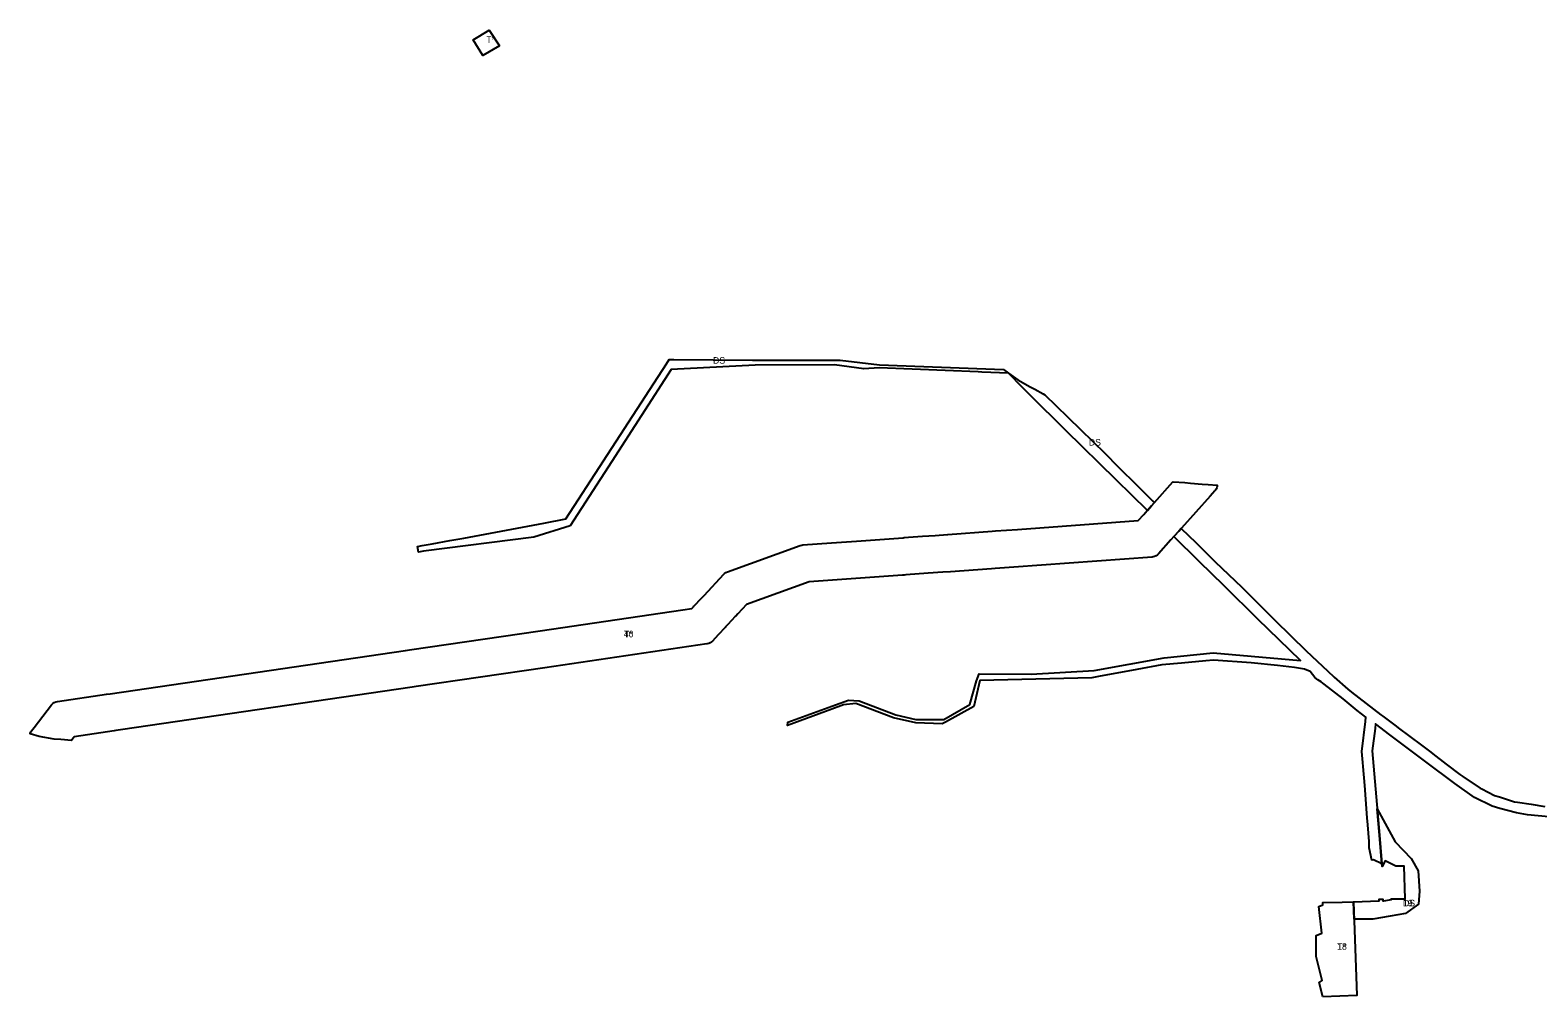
# Model space of a CAD drawing. Extents: x -501732 to -497665, y -1142022 to -1138283.
# Drawn here: x -501732 to -500116, y -1139555 to -1138520 of the extents above; entities that cross this region are included whole.
import ezdxf

# ---------------------------------------------------------------- set-up
doc = ezdxf.new("R2010")
doc.units = 0
for name, color, linetype in [('22', 7, 'Continuous'), ('23', 7, 'Continuous'), ('4', 7, 'Continuous'), ('5', 7, 'Continuous'), ('61', 7, 'Continuous')]:
    doc.layers.add(name, color=color, linetype=linetype)

msp = doc.modelspace()

# ---------------------------------------------------------------- linework, layer by layer
at = {"layer": '22'}
msp.add_lwpolyline([(-501229.22, -1138536.54), (-501247.04, -1138546.95), (-501257.65, -1138529.93), (-501240.34, -1138519.72)], close=True, dxfattribs=at)
at = {"layer": '23'}
for points in [[(-501685.107, -1139276.598), (-501687.932, -1139280.554), (-501699.61, -1139279.76), (-501706.69, -1139279.11), (-501722.83, -1139276.39), (-501732.363, -1139273.477), (-501732.227, -1139272.97), (-501731.49, -1139271.39), (-501730.748, -1139270.282), (-501728.156, -1139266.922), (-501709.368, -1139242.564), (-501709.11, -1139242.243), (-501707.878, -1139241.011), (-501706.45, -1139240.011), (-501704.87, -1139239.274), (-501703.186, -1139238.823), (-501702.899, -1139238.777), (-501650.54, -1139231.108), (-501646.694, -1139230.545), (-501329.931, -1139184.15), (-501325.68, -1139183.528), (-501185.811, -1139163.043), (-501032.686, -1139140.616), (-501023.323, -1139139.244), (-501023.184, -1139139.224), (-501021.521, -1139137.443), (-501020.9, -1139136.778), (-501012.489, -1139127.77), (-501010.776, -1139125.935), (-501010.148, -1139125.263), (-500988.975, -1139102.587), (-500988.094, -1139101.752), (-500986.666, -1139100.752), (-500985.077, -1139100.012), (-500907.03, -1139071.773), (-500905.364, -1139071.328), (-500904.35, -1139071.202), (-500873.537, -1139068.97), (-500846.877, -1139067.038), (-500796.648, -1139063.399), (-500795.663, -1139063.328), (-500790.906, -1139062.983), (-500776.044, -1139061.906), (-500762.248, -1139060.907), (-500749.043, -1139059.95), (-500748.884, -1139059.939), (-500701.361, -1139056.495), (-500697.809, -1139056.238), (-500674.038, -1139054.516), (-500544.867, -1139045.157), (-500538.809, -1139038.397), (-500535.273, -1139034.451), (-500534.979, -1139034.123), (-500530.492, -1139029.117), (-500527.748, -1139026.054), (-500527.506, -1139025.784), (-500507.761, -1139003.75), (-500507.486, -1139003.444), (-500494.966, -1139004.456), (-500488.74, -1139004.96), (-500476.13, -1139005.98), (-500469.926, -1139006.482), (-500459.996, -1139007.284), (-500460.078, -1139008.218), (-500460.529, -1139009.902), (-500461.266, -1139011.482), (-500462.266, -1139012.909), (-500462.482, -1139013.159), (-500462.675, -1139013.375), (-500467.756, -1139019.044), (-500498.442, -1139053.288), (-500498.684, -1139053.558), (-500501.17, -1139056.332), (-500506.124, -1139061.86), (-500506.461, -1139062.237), (-500509.726, -1139065.88), (-500523.165, -1139080.877), (-500524.184, -1139081.863), (-500525.612, -1139082.863), (-500527.192, -1139083.6), (-500528.876, -1139084.051), (-500529.889, -1139084.177), (-500677.925, -1139094.902), (-500697.933, -1139096.352), (-500701.951, -1139096.643), (-500745.895, -1139099.827), (-500745.928, -1139099.829), (-500754.338, -1139100.439), (-500769.796, -1139101.559), (-500793.941, -1139103.308), (-500795.728, -1139103.437), (-500797.329, -1139103.553), (-500897.322, -1139110.798), (-500964.668, -1139135.165), (-500973.726, -1139144.866), (-500976.202, -1139147.518), (-500976.624, -1139147.97), (-500984.545, -1139156.453), (-500986.987, -1139159.068), (-500987.43, -1139159.543), (-500994.806, -1139167.442), (-501001.124, -1139174.208), (-501002.005, -1139175.043), (-501003.433, -1139176.043), (-501005.013, -1139176.78), (-501006.697, -1139177.231), (-501006.984, -1139177.277), (-501180.616, -1139202.708), (-501318.665, -1139222.928), (-501322.972, -1139223.558), (-501635.553, -1139269.339), (-501640.555, -1139270.072), (-501642.492, -1139270.356)], [(-500346.946, -1139555.283), (-500350.98, -1139539.99), (-500347.67, -1139537.92), (-500354.24, -1139512.12), (-500354, -1139489.66), (-500348.12, -1139487.24), (-500351.18, -1139458.67), (-500346.85, -1139456.55), (-500346.97, -1139454.3), (-500326.25, -1139453.7), (-500314.141, -1139453.341), (-500310.579, -1139553.684)]]:
    msp.add_lwpolyline(points, close=True, dxfattribs=at)
at = {"layer": '4'}
for points in [[(-500958.02, -1138873.22), (-500864.37, -1138873.32), (-500822.15, -1138878.1), (-500689.04, -1138883.38), (-500683.78, -1138887.15), (-500712.46, -1138885.98), (-500716.26, -1138885.83), (-500822.3, -1138881.54), (-500838.85, -1138882.61), (-500870.26, -1138878.2), (-500955.45, -1138878.77), (-501045.47, -1138883.38), (-501109.11, -1138981.84), (-501153.49, -1139050.58), (-501192.69, -1139063.02), (-501310.73, -1139077.78), (-501316.033, -1139078.856), (-501317.39, -1139072.9), (-501312.11, -1139071.91), (-501301.5, -1139069.91), (-501282.39, -1139066.31), (-501267.53, -1139063.76), (-501181.96, -1139047.68), (-501158.18, -1139043.21), (-501117.79, -1138981), (-501050.36, -1138877.14), (-501047.44, -1138872.64), (-501046.03, -1138872.65), (-501042.62, -1138872.66)], [(-500527.506, -1139025.784), (-500527.748, -1139026.054), (-500530.492, -1139029.117), (-500534.979, -1139034.123), (-500568.41, -1139001.4), (-500622.23, -1138948.62), (-500639.621, -1138931.463), (-500643.79, -1138927.35), (-500652.2, -1138919.04), (-500668.76, -1138902.67), (-500683.78, -1138887.15), (-500673.89, -1138894.24), (-500660.45, -1138901.64), (-500655.49, -1138904.38), (-500646.82, -1138909.15), (-500644.84, -1138910.24), (-500633.048, -1138921.763), (-500580.28, -1138973.33), (-500566.46, -1138987.21), (-500564.53, -1138989.15), (-500558.24, -1138995.21), (-500553.73, -1138999.55), (-500529.16, -1139024.19)]]:
    msp.add_lwpolyline(points, close=True, dxfattribs=at)
msp.add_lwpolyline([(-500104.6, -1139362.45), (-500127.69, -1139360.35), (-500139.46, -1139358.15), (-500157.29, -1139353.6), (-500165.36, -1139350.86), (-500184.45, -1139341.68), (-500205.57, -1139326.61), (-500236.44, -1139303.68), (-500275.25, -1139274.69), (-500290.32, -1139262.81), (-500290.98, -1139267.72), (-500294.22, -1139291.73), (-500286.23, -1139382.13), (-500283.51, -1139412.96), (-500292.7, -1139408.67), (-500294.58, -1139409), (-500297.22, -1139395.52), (-500297.16, -1139388.91), (-500298.61, -1139371.04), (-500299.24, -1139363.35), (-500302.05, -1139328.71), (-500303.76, -1139308.69), (-500304.13, -1139304.15), (-500305.02, -1139292.6), (-500301.27, -1139260.38), (-500300.73, -1139255.77), (-500310.28, -1139248.53), (-500322.81, -1139237.66), (-500325.082, -1139235.915), (-500345.51, -1139220.23), (-500346.86, -1139219.27), (-500348.67, -1139217.99), (-500352.14, -1139215.54), (-500355.57, -1139213.12), (-500360.61, -1139206.92), (-500366.55, -1139204.22), (-500377.14, -1139202.32), (-500395.57, -1139200.38), (-500423.9, -1139197.35), (-500464.14, -1139194.72), (-500472.29, -1139195.46), (-500498.4, -1139197.81), (-500519.55, -1139199.72), (-500546.42, -1139204.65), (-500563.81, -1139207.84), (-500585.39, -1139211.8), (-500594.36, -1139213.44), (-500714.6, -1139216.57), (-500721.12, -1139244.16), (-500751.5, -1139260.89), (-500754.91, -1139262.77), (-500782.98, -1139261.63), (-500807.13, -1139256.24), (-500847.6, -1139241.06), (-500860.49, -1139242.36), (-500873.077, -1139246.973), (-500920.76, -1139264.45), (-500920.22, -1139261.14), (-500873.316, -1139243.924), (-500855.27, -1139237.3), (-500843.89, -1139238.16), (-500804.64, -1139253.34), (-500783.14, -1139258.04), (-500753.27, -1139258.36), (-500725.2, -1139242.04), (-500718.19, -1139216.67), (-500715.16, -1139209.22), (-500659.56, -1139209.52), (-500592.12, -1139205.52), (-500517.07, -1139192.04), (-500464.48, -1139186.64), (-500370.82, -1139194.87), (-500416.43, -1139150.64), (-500452.73, -1139115.11), (-500479.49, -1139088.98), (-500506.461, -1139062.237), (-500506.124, -1139061.86), (-500501.17, -1139056.332), (-500498.684, -1139053.558), (-500482.93, -1139068.74), (-500462.33, -1139089.14), (-500433.58, -1139116.46), (-500397.88, -1139152.21), (-500364.91, -1139184.6), (-500335.48, -1139212.19), (-500334.919, -1139212.675), (-500320.089, -1139225.511), (-500316.22, -1139228.86), (-500284.89, -1139253.07), (-500282.78, -1139254.64), (-500268.35, -1139265.35), (-500266.02, -1139267.1), (-500253.74, -1139276.29), (-500241.34, -1139285.57), (-500231.2, -1139293.17), (-500229.07, -1139294.81), (-500214.6, -1139305.92), (-500200.22, -1139316.97), (-500196.84, -1139319.25), (-500178.45, -1139331.63), (-500176.67, -1139332.53), (-500162.88, -1139339.45), (-500157.62, -1139341.12), (-500141.33, -1139346.29), (-500138.29, -1139346.76), (-500123.61, -1139349.03), (-500109.13, -1139351.26)], dxfattribs=at)
at = {"layer": '5'}
msp.add_lwpolyline([(-500313.478, -1139472.014), (-500314.141, -1139453.341), (-500286.45, -1139452.52), (-500286.72, -1139450.62), (-500282.74, -1139450.57), (-500282.45, -1139452.4), (-500281.71, -1139452.28), (-500273.5, -1139450.97), (-500273.58, -1139450.46), (-500258.73, -1139450.28), (-500259.7, -1139415.17), (-500268.51, -1139415.43), (-500275.77, -1139411.85), (-500280.25, -1139409.64), (-500283.28, -1139415.51), (-500283.51, -1139412.96), (-500286.23, -1139382.13), (-500288.717, -1139353.986), (-500269.511, -1139389.411), (-500252.289, -1139407.075), (-500244.782, -1139420.323), (-500243.457, -1139441.961), (-500244.34, -1139456.092), (-500258.3, -1139465.888), (-500274.81, -1139468.898), (-500293.357, -1139471.989)], close=True, dxfattribs=at)

# ---------------------------------------------------------------- texts
at = {"layer": '22'}
msp.add_text('T*', height=7, dxfattribs=at).set_placement((-501243.472, -1138533.314))
at = {"layer": '23'}
for p in [(-501096.12, -1139170.123), (-500331.605, -1139504.862)]:
    msp.add_text('T*', height=7, rotation=359.41537, dxfattribs=at).set_placement(p)
at = {"layer": '4'}
for p in [(-501000.501, -1138877.004), (-500597.716, -1138964.728)]:
    msp.add_text('DS', height=7, dxfattribs=at).set_placement(p)
at = {"layer": '5'}
msp.add_text('DS', height=7, dxfattribs=at).set_placement((-500261.043, -1139458.351))
at = {"layer": '61'}
for s, p in [('40', (-501096.112, -1139170.122)), ('19', (-500261.06, -1139458.351)), ('18', (-500331.597, -1139504.861))]:
    msp.add_text(s, height=7, dxfattribs=at).set_placement(p)

doc.saveas('drawing.dxf')
